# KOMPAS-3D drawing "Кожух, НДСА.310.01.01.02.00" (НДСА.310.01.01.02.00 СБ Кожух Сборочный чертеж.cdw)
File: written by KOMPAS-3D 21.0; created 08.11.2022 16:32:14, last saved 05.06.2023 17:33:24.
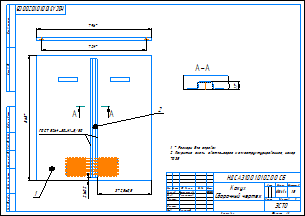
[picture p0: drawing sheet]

Sheet 1: A3, landscape

Document properties: Автор: adminzsc; Масса: 6.188608; 250211453674: <item xmlns="http://appius.ru/pdm" xmlns:xs="http://www.w3.org/2001/XMLSchema" xmlns:xsi="http://www.w3.org/2001/XMLSchema-instance" xsi:type="item">  <element xmlns:d2p1="http://v8.1c.ru/8.1/data/enterprise/current-config" xsi:type="d2p1:CatalogRef.aps_Элемен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; 250211453774: <item xmlns="http://appius.ru/pdm" xmlns:xs="http://www.w3.org/2001/XMLSchema" xmlns:xsi="http://www.w3.org/2001/XMLSchema-instance" xsi:type="item">  <element xmlns:d2p1="http://v8.1c.ru/8.1/data/enterprise/current-config" xsi:type="d2p1:CatalogRef.aps_Элемен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; 250211453874: <item xmlns="http://appius.ru/pdm" xmlns:xs="http://www.w3.org/2001/XMLSchema" xmlns:xsi="http://www.w3.org/2001/XMLSchema-instance" xsi:type="item">  <element xmlns:d2p1="http://v8.1c.ru/8.1/data/enterprise/current-config" xsi:type="d2p1:CatalogRef.aps_Элемен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; 352688346901: <item xmlns="http://appius.ru/pdm" xmlns:xs="http://www.w3.org/2001/XMLSchema" xmlns:xsi="http://www.w3.org/2001/XMLSchema-instance" xsi:type="item">  <element xmlns:d2p1="http://v8.1c.ru/8.1/data/enterprise/current-config" xsi:type="d2p1:CatalogRef.aps_Элемен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; 352688347001: <item xmlns="http://appius.ru/pdm" xmlns:xs="http://www.w3.org/2001/XMLSchema" xmlns:xsi="http://www.w3.org/2001/XMLSchema-instance" xsi:type="item">  <element xmlns:d2p1="http://v8.1c.ru/8.1/data/enterprise/current-config" xsi:type="d2p1:CatalogRef.aps_Элемен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; 352688347101: <item xmlns="http://appius.ru/pdm" xmlns:xs="http://www.w3.org/2001/XMLSchema" xmlns:xsi="http://www.w3.org/2001/XMLSchema-instance" xsi:type="item">  <element xmlns:d2p1="http://v8.1c.ru/8.1/data/enterprise/current-config" xsi:type="d2p1:CatalogRef.aps_Элемен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; PDM_DOCXDTO: <item xmlns="http://appius.ru/pdm" xmlns:xs="http://www.w3.org/2001/XMLSchema" xmlns:xsi="http://www.w3.org/2001/XMLSchema-instance" xsi:type="item">  <element xmlns:d2p1="http://v8.1c.ru/8.1/data/enterprise/current-config" xsi:type="d2p1:CatalogRef.aps_Элемен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; PDM_ITEMXDTO: <item xmlns="http://appius.ru/pdm" xmlns:xs="http://www.w3.org/2001/XMLSchema" xmlns:xsi="http://www.w3.org/2001/XMLSchema-instance" xsi:type="item">  <element xmlns:d2p1="http://v8.1c.ru/8.1/data/enterprise/current-config" xsi:type="d2p1:CatalogRef.aps_Элемен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; 312987600589: <item xmlns="http://appius.ru/pdm" xmlns:xs="http://www.w3.org/2001/XMLSchema" xmlns:xsi="http://www.w3.org/2001/XMLSchema-instance" xsi:type="item">  <element xmlns:d2p1="http://v8.1c.ru/8.1/data/enterprise/current-config" xsi:type="d2p1:CatalogRef.aps_Элемен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; Полное имя файла: НДСА.310.01.01.02.00 Кожух.a3d; PLM_CDWXDTO: <item xmlns="http://appius.ru/pdm" xmlns:xs="http://www.w3.org/2001/XMLSchema" xmlns:xsi="http://www.w3.org/2001/XMLSchema-instance" xsi:type="item">  <element xmlns:d2p1="http://v8.1c.ru/8.1/data/enterprise/current-config" xsi:type="d2p1:CatalogRef.aps_Элемен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

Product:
- Part/product: Кожух  | designation НДСА.310.01.01.02.00
    Масса: 6.188608
    additional columns: <item xmlns="http://appius.ru/pdm" xmlns:xs="http://www.w3.org/2001/XMLSchema" x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; <item xmlns="http://appius.ru/pdm" xmlns:xs="http://www.w3.org/2001/XMLSchema" x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; <item xmlns="http://appius.ru/pdm" xmlns:xs="http://www.w3.org/2001/XMLSchema" x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; <item xmlns="http://appius.ru/pdm" xmlns:xs="http://www.w3.org/2001/XMLSchema" x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; <item xmlns="http://appius.ru/pdm" xmlns:xs="http://www.w3.org/2001/XMLSchema" x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; <item xmlns="http://appius.ru/pdm" xmlns:xs="http://www.w3.org/2001/XMLSchema" x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; <item xmlns="http://appius.ru/pdm" xmlns:xs="http://www.w3.org/2001/XMLSchema" x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; <item xmlns="http://appius.ru/pdm" xmlns:xs="http://www.w3.org/2001/XMLSchema" x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
    source file: НДСА.310.01.01.02.00 Кожух.spw
  - Component [detail]: Крышка  | designation НДСА.310.01.01.02.01  | pos. 1  | Масса: 5.766009; Раздел спецификации: Детали; Форматы листов документа: A2; additional columns: <item xmlns="http://appius.ru/pdm" xmlns:xs="http://www.w3.org/2001/XMLSchema" x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; <item xmlns="http://appius.ru/pdm" xmlns:xs="http://www.w3.org/2001/XMLSchema" x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; <item xmlns="http://appius.ru/pdm" xmlns:xs="http://www.w3.org/2001/XMLSchema" x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; <item xmlns="http://appius.ru/pdm" xmlns:xs="http://www.w3.org/2001/XMLSchema" x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; <item xmlns="http://appius.ru/pdm" xmlns:xs="http://www.w3.org/2001/XMLSchema" x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; <item xmlns="http://appius.ru/pdm" xmlns:xs="http://www.w3.org/2001/XMLSchema" x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; <item xmlns="http://appius.ru/pdm" xmlns:xs="http://www.w3.org/2001/XMLSchema" x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; <item xmlns="http://appius.ru/pdm" xmlns:xs="http://www.w3.org/2001/XMLSchema" x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; source file: НДСА.310.01.01.02.01 Крышка.CDW, НДСА.310.01.01.02.01 Крышка.m3d
  - Component [detail]: Стяжка  | designation НДСА.875.03.00.00.02  | pos. 2  | Масса: 0.4226; Раздел спецификации: Детали; Форматы листов документа: A4; additional columns: <item xmlns="http://appius.ru/pdm" xmlns:xs="http://www.w3.org/2001/XMLSchema" x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; <item xmlns="http://appius.ru/pdm" xmlns:xs="http://www.w3.org/2001/XMLSchema" x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; <item xmlns="http://appius.ru/pdm" xmlns:xs="http://www.w3.org/2001/XMLSchema" x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; <item xmlns="http://appius.ru/pdm" xmlns:xs="http://www.w3.org/2001/XMLSchema" x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; <item xmlns="http://appius.ru/pdm" xmlns:xs="http://www.w3.org/2001/XMLSchema" x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; <item xmlns="http://appius.ru/pdm" xmlns:xs="http://www.w3.org/2001/XMLSchema" x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; <item xmlns="http://appius.ru/pdm" xmlns:xs="http://www.w3.org/2001/XMLSchema" x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; <item xmlns="http://appius.ru/pdm" xmlns:xs="http://www.w3.org/2001/XMLSchema" x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; source file: НДСА.875.03.00.00.02 Стяжка.cdw, НДСА.875.03.00.00.02 Стяжка.m3d

Title block, sheet 1: Наименование: Кожух / Сборочный чертеж; Масса: 6188,61 г; Количество листов документа: 1; organisation: ЭСТО; Форматы листов документа: A3; stored path: C:\PLM\НДСА.875.03.01.00.00 СБ Кожух Сборочный чертеж.cdw; Разработал: Степаненкова; Проверил: Горностаев; Утвердил: Белецкий; Разработал, date: 05.06.2023

Views: Проекционный вид 3, Проекционный вид 4, Разрез А-А
Referenced files in C:\Users\cherbakova\Desktop\Барсук\: НДСА.875.03.01.00.00 Кожух.a3d
Referenced files in C:\PLM\: НДСА.310.01.01.02.00 Кожух.a3d, НДСА.875.03.00.00.02 Стяжка.m3d, НДСА.310.01.01.02.01 Крышка.m3d, НДСА.310.01.01.02.01 Крышка.CDW, НДСА.875.03.00.00.02 Стяжка.cdw
Referenced files in C:\Users\cherbakova\Desktop\PLM\: НДСА.875.03.00.00.01 Крышка.m3d
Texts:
  ГОСТ 5264-80-Н1-5/50
  Линейный размер
  НДСА.310.01.01.02.00
  НДСА.310.01.01.02.01
  Крышка
  НДСА.875.03.00.00.02
  Стяжка
  НДСА.310.01.01.02.01 Крышка
  НДСА.875.03.00.00.02 Стяжка
  НДСА.310.01.01.02.00 Кожух
  Основной
Dimensions and other numbers on the sheet: 372,5±0,5; 21±0,2; 868; 1; 2; 796; 724; 11; 4; 1:5; 6188,61 г; 05.06.2023

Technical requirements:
  * Размеры для справок
  Покрытие эмаль светло-серая мелкоструктурированная, номер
